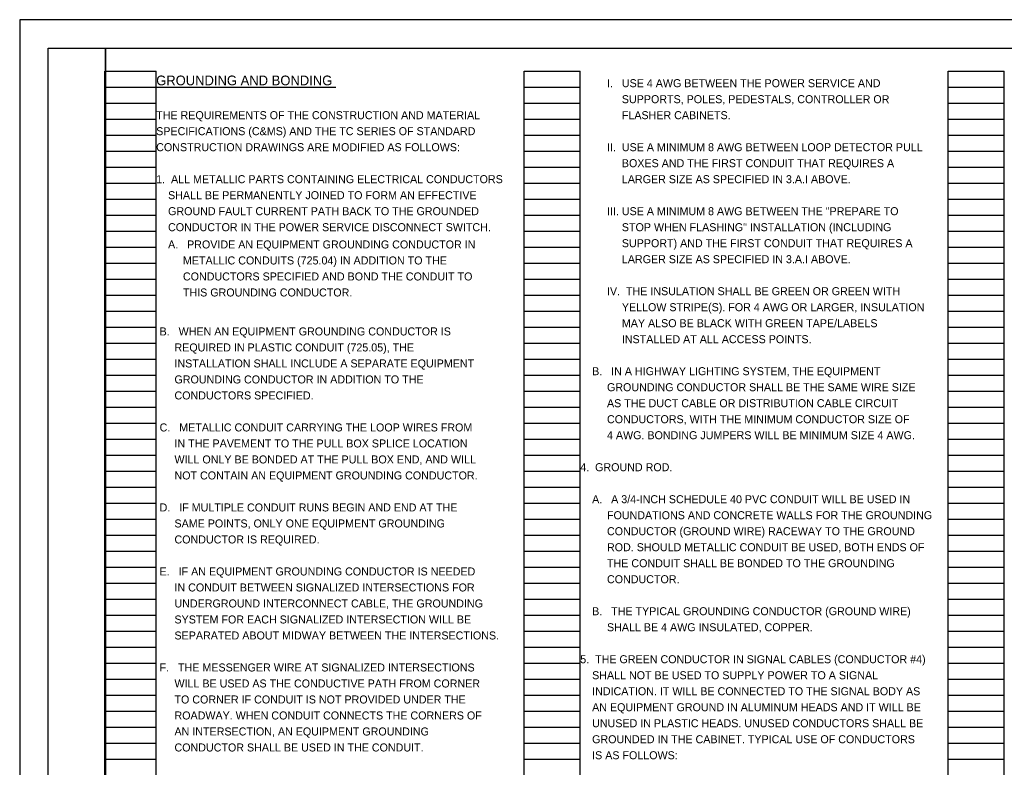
# Model space of a CAD drawing. Extents: x 0 to 34, y -2.4 to 22.
# Drawn here: x 0.01 to 17.24, y 8.96 to 22.04 of the extents above; entities that cross this region are included whole.
import ezdxf

# ---------------------------------------------------------------- set-up
doc = ezdxf.new("R2010")
doc.units = 0
for name, color, linetype in [('SH_Border', 7, 'Continuous'), ('SH_Cut_Line', 7, 'Continuous'), ('SH_Data', 7, 'Continuous'), ('SH_Text', 7, 'Continuous')]:
    doc.layers.add(name, color=color, linetype=linetype)

msp = doc.modelspace()

# ---------------------------------------------------------------- linework, layer by layer
at = {"layer": 'SH_Border'}
for points in [[(0.512, 21.541), (1.512, 21.541), (1.512, 0.541), (0.512, 0.541)], [(1.512, 21.541), (33.512, 21.541), (33.512, 0.541), (1.512, 0.541)]]:
    msp.add_lwpolyline(points, close=True, dxfattribs=at)
at = {"layer": 'SH_Cut_Line'}
msp.add_lwpolyline([(0.012, 0.041), (34.012, 0.041), (34.012, 22.041), (0.012, 22.041)], close=True, dxfattribs=at)
at = {"layer": 'SH_Data'}
for p, q in [((1.5, 0.98), (1.5, 21.14)), ((1.5, 21.14), (2.4, 21.14)), ((2.4, 0.98), (2.4, 21.14)), ((8.84, 0.98), (8.84, 21.14)), ((8.84, 21.14), (9.82, 21.14)), ((9.82, 0.98), (9.82, 21.14)), ((16.26, 0.98), (16.26, 21.14)), ((16.26, 21.14), (17.24, 21.14)), ((17.24, 0.98), (17.24, 21.14)), ((1.5, 20.86), (2.4, 20.86)), ((8.84, 20.86), (9.82, 20.86)), ((16.26, 20.86), (17.24, 20.86)), ((1.5, 20.58), (2.4, 20.58)), ((8.84, 20.58), (9.82, 20.58)), ((16.26, 20.58), (17.24, 20.58)), ((1.5, 20.3), (2.4, 20.3)), ((8.84, 20.3), (9.82, 20.3)), ((16.26, 20.3), (17.24, 20.3)), ((1.5, 20.02), (2.4, 20.02)), ((8.84, 20.02), (9.82, 20.02)), ((16.26, 20.02), (17.24, 20.02)), ((1.5, 19.74), (2.4, 19.74)), ((8.84, 19.74), (9.82, 19.74)), ((16.26, 19.74), (17.24, 19.74)), ((1.5, 19.46), (2.4, 19.46)), ((8.84, 19.46), (9.82, 19.46)), ((16.26, 19.46), (17.24, 19.46)), ((1.5, 19.18), (2.4, 19.18)), ((8.84, 19.18), (9.82, 19.18)), ((16.26, 19.18), (17.24, 19.18)), ((1.5, 18.9), (2.4, 18.9)), ((8.84, 18.9), (9.82, 18.9)), ((16.26, 18.9), (17.24, 18.9)), ((1.5, 18.62), (2.4, 18.62)), ((8.84, 18.62), (9.82, 18.62)), ((16.26, 18.62), (17.24, 18.62)), ((1.5, 18.34), (2.4, 18.34)), ((8.84, 18.34), (9.82, 18.34)), ((16.26, 18.34), (17.24, 18.34)), ((1.5, 18.06), (2.4, 18.06)), ((8.84, 18.06), (9.82, 18.06)), ((16.26, 18.06), (17.24, 18.06)), ((1.5, 17.78), (2.4, 17.78)), ((8.84, 17.78), (9.82, 17.78)), ((16.26, 17.78), (17.24, 17.78)), ((1.5, 17.5), (2.4, 17.5)), ((8.84, 17.5), (9.82, 17.5)), ((16.26, 17.5), (17.24, 17.5)), ((1.5, 17.22), (2.4, 17.22)), ((8.84, 17.22), (9.82, 17.22)), ((16.26, 17.22), (17.24, 17.22)), ((1.5, 16.94), (2.4, 16.94)), ((8.84, 16.94), (9.82, 16.94)), ((16.26, 16.94), (17.24, 16.94)), ((1.5, 16.66), (2.4, 16.66)), ((8.84, 16.66), (9.82, 16.66)), ((16.26, 16.66), (17.24, 16.66)), ((1.5, 16.38), (2.4, 16.38)), ((8.84, 16.38), (9.82, 16.38)), ((16.26, 16.38), (17.24, 16.38)), ((1.5, 16.1), (2.4, 16.1)), ((8.84, 16.1), (9.82, 16.1)), ((16.26, 16.1), (17.24, 16.1)), ((1.5, 15.82), (2.4, 15.82)), ((8.84, 15.82), (9.82, 15.82)), ((16.26, 15.82), (17.24, 15.82)), ((1.5, 15.54), (2.4, 15.54)), ((8.84, 15.54), (9.82, 15.54)), ((16.26, 15.54), (17.24, 15.54)), ((1.5, 15.26), (2.4, 15.26)), ((8.84, 15.26), (9.82, 15.26)), ((16.26, 15.26), (17.24, 15.26)), ((1.5, 14.98), (2.4, 14.98)), ((8.84, 14.98), (9.82, 14.98)), ((16.26, 14.98), (17.24, 14.98)), ((1.5, 14.7), (2.4, 14.7)), ((8.84, 14.7), (9.82, 14.7)), ((16.26, 14.7), (17.24, 14.7)), ((1.5, 14.42), (2.4, 14.42)), ((8.84, 14.42), (9.82, 14.42)), ((16.26, 14.42), (17.24, 14.42)), ((1.5, 14.14), (2.4, 14.14)), ((8.84, 14.14), (9.82, 14.14)), ((16.26, 14.14), (17.24, 14.14)), ((1.5, 13.86), (2.4, 13.86)), ((8.84, 13.86), (9.82, 13.86)), ((16.26, 13.86), (17.24, 13.86)), ((1.5, 13.58), (2.4, 13.58)), ((8.84, 13.58), (9.82, 13.58)), ((16.26, 13.58), (17.24, 13.58)), ((1.5, 13.3), (2.4, 13.3)), ((8.84, 13.3), (9.82, 13.3)), ((16.26, 13.3), (17.24, 13.3)), ((1.5, 13.02), (2.4, 13.02)), ((8.84, 13.02), (9.82, 13.02)), ((16.26, 13.02), (17.24, 13.02)), ((1.5, 12.74), (2.4, 12.74)), ((8.84, 12.74), (9.82, 12.74)), ((16.26, 12.74), (17.24, 12.74)), ((1.5, 12.46), (2.4, 12.46)), ((8.84, 12.46), (9.82, 12.46)), ((16.26, 12.46), (17.24, 12.46)), ((1.5, 12.18), (2.4, 12.18)), ((8.84, 12.18), (9.82, 12.18)), ((16.26, 12.18), (17.24, 12.18)), ((1.5, 11.9), (2.4, 11.9)), ((8.84, 11.9), (9.82, 11.9)), ((16.26, 11.9), (17.24, 11.9)), ((1.5, 11.62), (2.4, 11.62)), ((8.84, 11.62), (9.82, 11.62)), ((16.26, 11.62), (17.24, 11.62)), ((1.5, 11.34), (2.4, 11.34)), ((8.84, 11.34), (9.82, 11.34)), ((16.26, 11.34), (17.24, 11.34)), ((1.5, 11.06), (2.4, 11.06)), ((8.84, 11.06), (9.82, 11.06)), ((16.26, 11.06), (17.24, 11.06)), ((1.5, 10.78), (2.4, 10.78)), ((8.84, 10.78), (9.82, 10.78)), ((16.26, 10.78), (17.24, 10.78)), ((1.5, 10.5), (2.4, 10.5)), ((8.84, 10.5), (9.82, 10.5)), ((16.26, 10.5), (17.24, 10.5)), ((1.5, 10.22), (2.4, 10.22)), ((8.84, 10.22), (9.82, 10.22)), ((16.26, 10.22), (17.24, 10.22)), ((1.5, 9.94), (2.4, 9.94)), ((8.84, 9.94), (9.82, 9.94)), ((16.26, 9.94), (17.24, 9.94)), ((1.5, 9.66), (2.4, 9.66)), ((8.84, 9.66), (9.82, 9.66)), ((16.26, 9.66), (17.24, 9.66)), ((1.5, 9.38), (2.4, 9.38)), ((8.84, 9.38), (9.82, 9.38)), ((16.26, 9.38), (17.24, 9.38)), ((1.5, 9.1), (2.4, 9.1)), ((8.84, 9.1), (9.82, 9.1)), ((16.26, 9.1), (17.24, 9.1))]:
    msp.add_line(p, q, dxfattribs=at)
at = {"layer": 'SH_Text'}
msp.add_line((2.4, 20.86), (5.546, 20.86), dxfattribs=at)

# ---------------------------------------------------------------- texts
for s, height, p in [('GROUNDING AND BONDING', 0.17, (2.4, 20.893)), ('         I.   USE 4 AWG BETWEEN THE POWER SERVICE AND', 0.14, (9.82, 20.86)), ('              SUPPORTS, POLES, PEDESTALS, CONTROLLER OR', 0.14, (9.82, 20.58)), ('THE REQUIREMENTS OF THE CONSTRUCTION AND MATERIAL', 0.14, (2.4, 20.3)), ('              FLASHER CABINETS.', 0.14, (9.82, 20.3)), ('SPECIFICATIONS (C&MS) AND THE TC SERIES OF STANDARD', 0.14, (2.4, 20.02)), ('CONSTRUCTION DRAWINGS ARE MODIFIED AS FOLLOWS:', 0.14, (2.4, 19.74)), ('         II.  USE A MINIMUM 8 AWG BETWEEN LOOP DETECTOR PULL', 0.14, (9.82, 19.74)), ('              BOXES AND THE FIRST CONDUIT THAT REQUIRES A', 0.14, (9.82, 19.46)), ('1.  ALL METALLIC PARTS CONTAINING ELECTRICAL CONDUCTORS', 0.14, (2.4, 19.18)), ('              LARGER SIZE AS SPECIFIED IN 3.A.I ABOVE.', 0.14, (9.82, 19.18)), ('    SHALL BE PERMANENTLY JOINED TO FORM AN EFFECTIVE', 0.14, (2.4, 18.9)), ('    GROUND FAULT CURRENT PATH BACK TO THE GROUNDED', 0.14, (2.4, 18.62)), ('         III. USE A MINIMUM 8 AWG BETWEEN THE "PREPARE TO', 0.14, (9.82, 18.62)), ('    CONDUCTOR IN THE POWER SERVICE DISCONNECT SWITCH.', 0.14, (2.4, 18.34)), ('              STOP WHEN FLASHING" INSTALLATION (INCLUDING', 0.14, (9.82, 18.34)), ('    A.   PROVIDE AN EQUIPMENT GROUNDING CONDUCTOR IN', 0.14, (2.4, 18.038)), ('              SUPPORT) AND THE FIRST CONDUIT THAT REQUIRES A', 0.14, (9.82, 18.06)), ('              LARGER SIZE AS SPECIFIED IN 3.A.I ABOVE.', 0.14, (9.82, 17.78)), ('         METALLIC CONDUITS (725.04) IN ADDITION TO THE', 0.14, (2.4, 17.758)), ('         CONDUCTORS SPECIFIED AND BOND THE CONDUIT TO', 0.14, (2.4, 17.478)), ('         THIS GROUNDING CONDUCTOR.', 0.14, (2.4, 17.198)), ('         IV.  THE INSULATION SHALL BE GREEN OR GREEN WITH', 0.14, (9.82, 17.22)), ('              YELLOW STRIPE(S). FOR 4 AWG OR LARGER, INSULATION', 0.14, (9.82, 16.94)), ('              MAY ALSO BE BLACK WITH GREEN TAPE/LABELS', 0.14, (9.82, 16.66)), ('    B.   WHEN AN EQUIPMENT GROUNDING CONDUCTOR IS', 0.14, (2.252, 16.516)), ('         REQUIRED IN PLASTIC CONDUIT (725.05), THE', 0.14, (2.252, 16.236)), ('              INSTALLED AT ALL ACCESS POINTS.', 0.14, (9.82, 16.38)), ('         INSTALLATION SHALL INCLUDE A SEPARATE EQUIPMENT', 0.14, (2.252, 15.956)), ('    B.   IN A HIGHWAY LIGHTING SYSTEM, THE EQUIPMENT', 0.14, (9.82, 15.82)), ('         GROUNDING CONDUCTOR IN ADDITION TO THE', 0.14, (2.252, 15.676)), ('         GROUNDING CONDUCTOR SHALL BE THE SAME WIRE SIZE', 0.14, (9.82, 15.54)), ('         CONDUCTORS SPECIFIED.', 0.14, (2.252, 15.396)), ('         AS THE DUCT CABLE OR DISTRIBUTION CABLE CIRCUIT', 0.14, (9.82, 15.26)), ('         CONDUCTORS, WITH THE MINIMUM CONDUCTOR SIZE OF', 0.14, (9.82, 14.98)), ('    C.   METALLIC CONDUIT CARRYING THE LOOP WIRES FROM', 0.14, (2.252, 14.836)), ('         4 AWG. BONDING JUMPERS WILL BE MINIMUM SIZE 4 AWG.', 0.14, (9.82, 14.7)), ('         IN THE PAVEMENT TO THE PULL BOX SPLICE LOCATION', 0.14, (2.252, 14.556)), ('         WILL ONLY BE BONDED AT THE PULL BOX END, AND WILL', 0.14, (2.252, 14.276)), ('         NOT CONTAIN AN EQUIPMENT GROUNDING CONDUCTOR.', 0.14, (2.252, 13.996)), ('4.  GROUND ROD.', 0.14, (9.82, 14.14)), ('    A.   A 3/4-INCH SCHEDULE 40 PVC CONDUIT WILL BE USED IN', 0.14, (9.82, 13.58)), ('    D.   IF MULTIPLE CONDUIT RUNS BEGIN AND END AT THE', 0.14, (2.252, 13.436)), ('         FOUNDATIONS AND CONCRETE WALLS FOR THE GROUNDING', 0.14, (9.82, 13.3)), ('         SAME POINTS, ONLY ONE EQUIPMENT GROUNDING', 0.14, (2.252, 13.156)), ('         CONDUCTOR (GROUND WIRE) RACEWAY TO THE GROUND', 0.14, (9.82, 13.02)), ('         CONDUCTOR IS REQUIRED.', 0.14, (2.252, 12.876)), ('         ROD. SHOULD METALLIC CONDUIT BE USED, BOTH ENDS OF', 0.14, (9.82, 12.74)), ('         THE CONDUIT SHALL BE BONDED TO THE GROUNDING', 0.14, (9.82, 12.46)), ('    E.   IF AN EQUIPMENT GROUNDING CONDUCTOR IS NEEDED', 0.14, (2.252, 12.316)), ('         CONDUCTOR.', 0.14, (9.82, 12.18)), ('         IN CONDUIT BETWEEN SIGNALIZED INTERSECTIONS FOR', 0.14, (2.252, 12.036)), ('         UNDERGROUND INTERCONNECT CABLE, THE GROUNDING', 0.14, (2.252, 11.756)), ('    B.   THE TYPICAL GROUNDING CONDUCTOR (GROUND WIRE)', 0.14, (9.82, 11.62)), ('         SYSTEM FOR EACH SIGNALIZED INTERSECTION WILL BE', 0.14, (2.252, 11.476)), ('         SHALL BE 4 AWG INSULATED, COPPER.', 0.14, (9.82, 11.34)), ('         SEPARATED ABOUT MIDWAY BETWEEN THE INTERSECTIONS.', 0.14, (2.252, 11.196)), ('5.  THE GREEN CONDUCTOR IN SIGNAL CABLES (CONDUCTOR #4)', 0.14, (9.82, 10.78)), ('    F.   THE MESSENGER WIRE AT SIGNALIZED INTERSECTIONS', 0.14, (2.252, 10.636)), ('    SHALL NOT BE USED TO SUPPLY POWER TO A SIGNAL', 0.14, (9.82, 10.5)), ('         WILL BE USED AS THE CONDUCTIVE PATH FROM CORNER', 0.14, (2.252, 10.356)), ('    INDICATION. IT WILL BE CONNECTED TO THE SIGNAL BODY AS', 0.14, (9.82, 10.22)), ('         TO CORNER IF CONDUIT IS NOT PROVIDED UNDER THE', 0.14, (2.252, 10.076)), ('    AN EQUIPMENT GROUND IN ALUMINUM HEADS AND IT WILL BE', 0.14, (9.82, 9.94)), ('         ROADWAY. WHEN CONDUIT CONNECTS THE CORNERS OF', 0.14, (2.252, 9.796)), ('         AN INTERSECTION, AN EQUIPMENT GROUNDING', 0.14, (2.252, 9.516)), ('    UNUSED IN PLASTIC HEADS. UNUSED CONDUCTORS SHALL BE', 0.14, (9.82, 9.66)), ('    GROUNDED IN THE CABINET. TYPICAL USE OF CONDUCTORS', 0.14, (9.82, 9.38)), ('         CONDUCTOR SHALL BE USED IN THE CONDUIT.', 0.14, (2.252, 9.236)), ('    IS AS FOLLOWS:', 0.14, (9.82, 9.1))]:
    msp.add_text(s, height=height, dxfattribs=at).set_placement(p)

doc.saveas('drawing.dxf')
